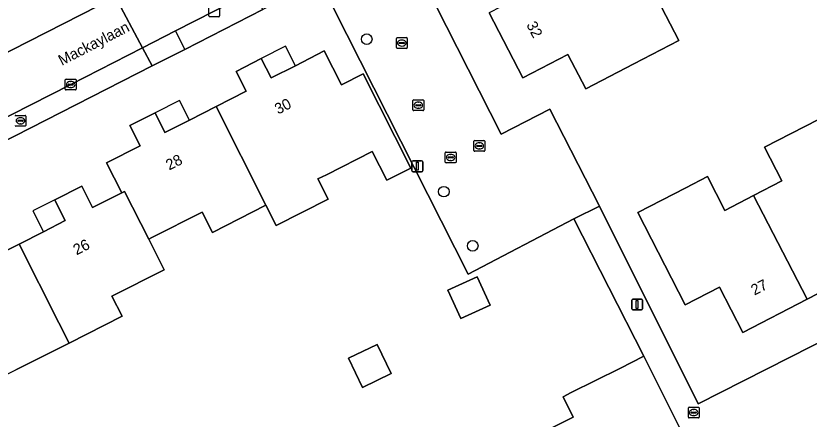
# Model space of a CAD drawing. Extents: x 162722 to 165104, y 384719 to 386284.
# Drawn here: x 163852.8 to 163926.1, y 385053.7 to 385090.9 of the extents above; entities that cross this region are included whole.
import ezdxf

# ---------------------------------------------------------------- set-up
doc = ezdxf.new("R2010")
doc.units = 0
for name, color, linetype in [('IMGEO_Boom', 7, 'Continuous'), ('IMGEO_Brandkraan', 7, 'Continuous'), ('IMGEO_Erf', 7, 'Continuous'), ('IMGEO_Kolk', 7, 'Continuous'), ('IMGEO_Lichtmast', 7, 'Continuous'), ('IMGEO_Openbare_ruimte_label', 7, 'Continuous'), ('IMGEO_Pand', 7, 'Continuous'), ('IMGEO_Pand_nummerreeks', 7, 'Continuous'), ('IMGEO_Pand_overbouw', 7, 'Continuous'), ('IMGEO_Parkeervlak_open', 7, 'Continuous'), ('IMGEO_Rijbaan_lokaal_open', 7, 'Continuous'), ('IMGEO_Rioolput', 7, 'Continuous'), ('IMGEO_Voetpad_open', 7, 'Continuous')]:
    doc.layers.add(name, color=color, linetype=linetype)

msp = doc.modelspace()

# ---------------------------------------------------------------- linework, layer by layer
at = {"layer": 'IMGEO_Boom'}
for centre in [(163885.184, 385088.775), (163892.305, 385074.695), (163894.978, 385069.688)]:
    msp.add_circle(centre, 0.489, dxfattribs=at)
at = {"layer": 'IMGEO_Brandkraan'}
for p, q in [((163852.761, 385081.738), (163853.613, 385081.738)), ((163852.945, 385081.232), (163852.945, 385081.244)), ((163853.383, 385081.195), (163852.985, 385081.195)), ((163852.988, 385081.281), (163853.386, 385081.281)), ((163853.174, 385081.518), (163853.199, 385081.518)), ((163853.429, 385081.244), (163853.429, 385081.232)), ((163853.687, 385081.664), (163853.687, 385080.812)), ((163853.613, 385080.738), (163852.761, 385080.738)), ((163853.197, 385080.958), (163853.172, 385080.958)), ((163914.978, 385054.796), (163915.83, 385054.796)), ((163914.903, 385053.87), (163914.903, 385054.722)), ((163915.162, 385054.29), (163915.162, 385054.302)), ((163915.6, 385054.253), (163915.202, 385054.253)), ((163915.205, 385054.339), (163915.603, 385054.339)), ((163915.391, 385054.576), (163915.416, 385054.576)), ((163915.646, 385054.302), (163915.646, 385054.29)), ((163915.904, 385054.722), (163915.904, 385053.87)), ((163915.83, 385053.796), (163914.978, 385053.796)), ((163915.414, 385054.016), (163915.389, 385054.016))]:
    msp.add_line(p, q, dxfattribs=at)
for points in [[(163852.761, 385081.738), (163853.613, 385081.738)], [(163853.687, 385081.664), (163853.687, 385080.812)], [(163853.613, 385080.738), (163852.761, 385080.738)], [(163914.978, 385054.796), (163915.83, 385054.796)], [(163914.903, 385053.87), (163914.903, 385054.722)], [(163915.904, 385054.722), (163915.904, 385053.87)], [(163915.83, 385053.796), (163914.978, 385053.796)]]:
    msp.add_lwpolyline(points, dxfattribs=at)
for centre, radius, start, end in [((163852.763, 385081.662), 0.0765, 91.55205, 178.44795), ((163852.763, 385081.662), 0.0765, 91.55205, 178.44795), ((163852.985, 385081.241), 0.0403, 85.87752, 175.75265), ((163852.982, 385081.231), 0.0366, 178.93798, 274.71019), ((163853.386, 385081.238), 0.043, 264.86636, 352.45326), ((163853.39, 385081.243), 0.0386, 1.73085, 96.63898), ((163853.611, 385081.662), 0.0765, 1.55205, 88.44795), ((163853.611, 385081.662), 0.0765, 1.55205, 88.44795), ((163852.763, 385080.814), 0.0765, 181.55205, 268.44795), ((163852.763, 385080.814), 0.0765, 181.55205, 268.44795), ((163853.611, 385080.814), 0.0765, 271.55205, 358.44795), ((163853.611, 385080.814), 0.0765, 271.55205, 358.44795), ((163914.98, 385054.72), 0.0765, 91.55205, 178.44795), ((163914.98, 385054.72), 0.0765, 91.55205, 178.44795), ((163915.828, 385054.72), 0.0765, 1.55205, 88.44795), ((163915.828, 385054.72), 0.0765, 1.55205, 88.44795), ((163915.202, 385054.299), 0.0403, 85.87752, 175.75265), ((163915.199, 385054.289), 0.0366, 178.93798, 274.71019), ((163915.603, 385054.296), 0.043, 264.86636, 352.45326), ((163915.607, 385054.301), 0.0386, 1.73085, 96.63898), ((163914.98, 385053.872), 0.0765, 181.55205, 268.44795), ((163914.98, 385053.872), 0.0765, 181.55205, 268.44795), ((163915.828, 385053.872), 0.0765, 271.55205, 358.44795), ((163915.828, 385053.872), 0.0765, 271.55205, 358.44795)]:
    msp.add_arc(centre, radius, start, end, dxfattribs=at)
for centre, major_axis, ratio, start_param, end_param in [((163853.173, 385081.238), (-0.387, 0.002), 0.722429, 4.712389, 7.853982), ((163853.198, 385081.238), (-0.39, 0.002), 0.717154, 1.570796, 4.712389), ((163915.39, 385054.296), (-0.387, 0.002), 0.722429, 4.712389, 7.853982), ((163915.415, 385054.296), (-0.39, 0.002), 0.717154, 1.570796, 4.712389)]:
    msp.add_ellipse(centre, major_axis=major_axis, ratio=ratio, start_param=start_param, end_param=end_param, dxfattribs=at)
at = {"layer": 'IMGEO_Erf'}
for points in [[(163882.314, 385121.11), (163885.455, 385114.979), (163893.028, 385100.308), (163888.495, 385097.974), (163897.601, 385079.99), (163902.096, 385082.296), (163906.672, 385073.409), (163906.693, 385073.366), (163915.816, 385055.107), (163938.946, 385066.833)], [(163844.323, 385083.699), (163845.913, 385084.495), (163861.973, 385092.689), (163879.735, 385101.752)], [(163910.786, 385094.89), (163914.022, 385088.652), (163909.858, 385086.492), (163905.419, 385084.19), (163903.77, 385087.369), (163899.61, 385085.211), (163896.499, 385091.208)], [(163899.686, 385051.591), (163904.266, 385053.887), (163903.329, 385055.755), (163904.089, 385056.136), (163908.558, 385058.376), (163910.795, 385059.494), (163904.326, 385072.183), (163894.544, 385067.072), (163880.854, 385094.169), (163878.622, 385093.046), (163875.596, 385091.501), (163868.387, 385087.828), (163865.359, 385086.309), (163851.324, 385079.151)], [(163850.057, 385068.328), (163853.059, 385069.852), (163855.314, 385070.997), (163857.331, 385072.021), (163856.376, 385073.904), (163856.356, 385073.944), (163858.844, 385075.207), (163859.85, 385073.227), (163862.538, 385074.592), (163861.139, 385077.348), (163864.257, 385078.931), (163863.307, 385080.802), (163865.619, 385081.976), (163866.538, 385080.166), (163868.8, 385081.297), (163871.258, 385082.545), (163874.042, 385083.959), (163873.106, 385085.803), (163875.44, 385086.989), (163876.354, 385085.191), (163878.589, 385086.326), (163881.259, 385087.682), (163882.849, 385084.552), (163884.865, 385085.567), (163889.273, 385076.87), (163887.04, 385075.746), (163885.687, 385078.414), (163881.451, 385076.263), (163880.671, 385075.867), (163881.617, 385074.004), (163876.82, 385071.568), (163875.874, 385073.435), (163870.931, 385070.924), (163869.976, 385072.803), (163865.335, 385070.447), (163865.034, 385070.295), (163866.457, 385067.487), (163861.641, 385065.042), (163862.579, 385063.193), (163857.691, 385060.711), (163852.747, 385058.247)]]:
    msp.add_lwpolyline(points, dxfattribs=at)
for points in [[(163932.499, 385073.497), (163929.642, 385072.024), (163931.809, 385067.822), (163925.868, 385064.758), (163919.927, 385061.695), (163917.775, 385065.867), (163914.617, 385064.238), (163910.224, 385072.757), (163914.668, 385075.049), (163916.677, 385076.085), (163918.286, 385072.966), (163920.934, 385074.332), (163923.551, 385075.682), (163921.948, 385078.788), (163928.127, 385081.975), (163930.207, 385077.941)], [(163892.693, 385065.585), (163895.401, 385066.822), (163896.589, 385064.222), (163893.881, 385062.985)], [(163883.496, 385059.309), (163886.14, 385060.596), (163887.449, 385057.906), (163884.805, 385056.62)]]:
    msp.add_lwpolyline(points, close=True, dxfattribs=at)
at = {"layer": 'IMGEO_Kolk'}
for p, q in [((163870.591, 385090.925), (163870.591, 385091.777)), ((163871.592, 385091.777), (163871.592, 385090.925)), ((163871.518, 385090.851), (163870.666, 385090.851)), ((163887.927, 385087.99), (163887.927, 385088.842)), ((163888.002, 385088.916), (163888.854, 385088.916)), ((163888.415, 385088.696), (163888.44, 385088.696)), ((163888.928, 385088.842), (163888.928, 385087.99)), ((163888.854, 385087.916), (163888.002, 385087.916)), ((163888.186, 385088.41), (163888.186, 385088.422)), ((163888.624, 385088.373), (163888.226, 385088.373)), ((163888.229, 385088.459), (163888.627, 385088.459)), ((163888.438, 385088.136), (163888.413, 385088.136)), ((163888.67, 385088.422), (163888.67, 385088.41)), ((163857.33, 385084.156), (163857.33, 385085.008)), ((163857.405, 385085.082), (163858.257, 385085.082)), ((163857.818, 385084.862), (163857.843, 385084.862)), ((163858.331, 385085.008), (163858.331, 385084.156)), ((163857.589, 385084.576), (163857.589, 385084.588)), ((163858.027, 385084.539), (163857.629, 385084.539)), ((163857.632, 385084.625), (163858.03, 385084.625)), ((163857.841, 385084.302), (163857.816, 385084.302)), ((163858.073, 385084.588), (163858.073, 385084.576)), ((163858.257, 385084.082), (163857.405, 385084.082)), ((163895.083, 385078.494), (163895.083, 385079.346)), ((163895.158, 385079.42), (163896.01, 385079.42)), ((163895.385, 385078.963), (163895.783, 385078.963)), ((163895.571, 385079.2), (163895.596, 385079.2)), ((163896.084, 385079.346), (163896.084, 385078.494)), ((163896.01, 385078.42), (163895.158, 385078.42)), ((163895.342, 385078.914), (163895.342, 385078.926)), ((163895.78, 385078.877), (163895.382, 385078.877)), ((163895.594, 385078.64), (163895.569, 385078.64)), ((163895.826, 385078.926), (163895.826, 385078.914))]:
    msp.add_line(p, q, dxfattribs=at)
for points in [[(163870.591, 385090.925), (163870.591, 385091.777)], [(163871.592, 385091.777), (163871.592, 385090.925)], [(163871.518, 385090.851), (163870.666, 385090.851)], [(163887.927, 385087.99), (163887.927, 385088.842)], [(163888.002, 385088.916), (163888.854, 385088.916)], [(163888.928, 385088.842), (163888.928, 385087.99)], [(163888.854, 385087.916), (163888.002, 385087.916)], [(163857.33, 385084.156), (163857.33, 385085.008)], [(163857.405, 385085.082), (163858.257, 385085.082)], [(163858.331, 385085.008), (163858.331, 385084.156)], [(163858.257, 385084.082), (163857.405, 385084.082)], [(163895.083, 385078.494), (163895.083, 385079.346)], [(163895.158, 385079.42), (163896.01, 385079.42)], [(163896.084, 385079.346), (163896.084, 385078.494)], [(163896.01, 385078.42), (163895.158, 385078.42)]]:
    msp.add_lwpolyline(points, dxfattribs=at)
for centre, radius, start, end in [((163870.668, 385090.927), 0.0765, 181.55205, 268.44795), ((163870.668, 385090.927), 0.0765, 181.55205, 268.44795), ((163871.516, 385090.927), 0.0765, 271.55205, 358.44795), ((163871.516, 385090.927), 0.0765, 271.55205, 358.44795), ((163888.004, 385088.84), 0.0765, 91.55205, 178.44795), ((163888.004, 385088.84), 0.0765, 91.55205, 178.44795), ((163888.852, 385088.84), 0.0765, 1.55205, 88.44795), ((163888.852, 385088.84), 0.0765, 1.55205, 88.44795), ((163888.004, 385087.992), 0.0765, 181.55205, 268.44795), ((163888.004, 385087.992), 0.0765, 181.55205, 268.44795), ((163888.226, 385088.419), 0.0403, 85.87752, 175.75265), ((163888.223, 385088.409), 0.0366, 178.93798, 274.71019), ((163888.627, 385088.416), 0.043, 264.86636, 352.45326), ((163888.631, 385088.421), 0.0386, 1.73085, 96.63898), ((163888.852, 385087.992), 0.0765, 271.55205, 358.44795), ((163888.852, 385087.992), 0.0765, 271.55205, 358.44795), ((163857.407, 385085.006), 0.0765, 91.55205, 178.44795), ((163857.407, 385085.006), 0.0765, 91.55205, 178.44795), ((163858.255, 385085.006), 0.0765, 1.55205, 88.44795), ((163858.255, 385085.006), 0.0765, 1.55205, 88.44795), ((163857.407, 385084.158), 0.0765, 181.55205, 268.44795), ((163857.407, 385084.158), 0.0765, 181.55205, 268.44795), ((163857.629, 385084.585), 0.0403, 85.87752, 175.75265), ((163857.626, 385084.575), 0.0366, 178.93798, 274.71019), ((163858.03, 385084.582), 0.043, 264.86636, 352.45326), ((163858.034, 385084.587), 0.0386, 1.73085, 96.63898), ((163858.255, 385084.158), 0.0765, 271.55205, 358.44795), ((163858.255, 385084.158), 0.0765, 271.55205, 358.44795), ((163895.16, 385079.344), 0.0765, 91.55205, 178.44795), ((163895.16, 385079.344), 0.0765, 91.55205, 178.44795), ((163895.382, 385078.923), 0.0403, 85.87752, 175.75265), ((163895.787, 385078.925), 0.0386, 1.73085, 96.63898), ((163896.008, 385079.344), 0.0765, 1.55205, 88.44795), ((163896.008, 385079.344), 0.0765, 1.55205, 88.44795), ((163895.16, 385078.496), 0.0765, 181.55205, 268.44795), ((163895.16, 385078.496), 0.0765, 181.55205, 268.44795), ((163895.379, 385078.913), 0.0366, 178.93798, 274.71019), ((163895.783, 385078.92), 0.043, 264.86636, 352.45326), ((163896.008, 385078.496), 0.0765, 271.55205, 358.44795), ((163896.008, 385078.496), 0.0765, 271.55205, 358.44795)]:
    msp.add_arc(centre, radius, start, end, dxfattribs=at)
for centre, major_axis, ratio, start_param, end_param in [((163888.414, 385088.416), (-0.387, 0.002), 0.722429, 4.712389, 7.853982), ((163888.439, 385088.416), (-0.39, 0.002), 0.717154, 1.570796, 4.712389), ((163857.817, 385084.582), (-0.387, 0.002), 0.722429, 4.712389, 7.853982), ((163857.842, 385084.582), (-0.39, 0.002), 0.717154, 1.570796, 4.712389), ((163895.57, 385078.92), (-0.387, 0.002), 0.722429, 4.712389, 7.853982), ((163895.595, 385078.92), (-0.39, 0.002), 0.717154, 1.570796, 4.712389)]:
    msp.add_ellipse(centre, major_axis=major_axis, ratio=ratio, start_param=start_param, end_param=end_param, dxfattribs=at)
at = {"layer": 'IMGEO_Lichtmast'}
for p, q in [((163889.464, 385077.54), (163890.254, 385077.54)), ((163890.254, 385077.54), (163889.464, 385077.54)), ((163889.364, 385076.64), (163889.364, 385077.44)), ((163889.364, 385077.44), (163889.364, 385076.64)), ((163890.354, 385077.44), (163890.354, 385076.64)), ((163890.354, 385076.64), (163890.354, 385077.44)), ((163890.254, 385076.54), (163889.464, 385076.54)), ((163889.464, 385076.54), (163890.254, 385076.54)), ((163909.671, 385063.876), (163909.671, 385064.676)), ((163909.671, 385064.676), (163909.671, 385063.876)), ((163909.771, 385064.776), (163910.561, 385064.776)), ((163910.561, 385064.776), (163909.771, 385064.776)), ((163910.661, 385064.676), (163910.661, 385063.876)), ((163910.661, 385063.876), (163910.661, 385064.676)), ((163910.561, 385063.776), (163909.771, 385063.776)), ((163909.771, 385063.776), (163910.561, 385063.776))]:
    msp.add_line(p, q, dxfattribs=at)
for points in [[(163889.784, 385077.415), (163889.934, 385077.415), (163889.934, 385076.665), (163889.784, 385076.665), (163889.784, 385077.415)], [(163910.091, 385064.651), (163910.241, 385064.651), (163910.241, 385063.901), (163910.091, 385063.901), (163910.091, 385064.651)]]:
    msp.add_lwpolyline(points, dxfattribs=at)
for centre, start, end in [((163889.464, 385077.44), 90, 180), ((163889.464, 385077.44), 90, 180), ((163890.254, 385077.44), 0, 90), ((163890.254, 385077.44), 360, 90), ((163889.464, 385076.64), 180, 270), ((163889.464, 385076.64), 180, 270), ((163890.254, 385076.64), 270, 0), ((163890.254, 385076.64), 270, 0), ((163909.771, 385064.676), 90, 180), ((163909.771, 385064.676), 90, 180), ((163910.561, 385064.676), 0, 90), ((163910.561, 385064.676), 360, 90), ((163909.771, 385063.876), 180, 270), ((163909.771, 385063.876), 180, 270), ((163910.561, 385063.876), 270, 0), ((163910.561, 385063.876), 270, 0)]:
    msp.add_arc(centre, 0.1, start, end, dxfattribs=at)
at = {"layer": 'IMGEO_Pand'}
for points in [[(163896.499, 385091.208), (163899.61, 385085.211), (163903.77, 385087.369), (163905.419, 385084.19), (163909.858, 385086.492), (163914.022, 385088.652), (163910.786, 385094.89), (163907.719, 385093.299), (163906.196, 385096.235)], [(163884.865, 385085.567), (163882.849, 385084.552), (163881.259, 385087.682), (163878.589, 385086.326), (163876.354, 385085.191), (163875.44, 385086.989), (163873.106, 385085.803), (163874.042, 385083.959), (163871.258, 385082.545), (163875.874, 385073.435), (163876.82, 385071.568), (163881.617, 385074.004), (163880.671, 385075.867), (163881.451, 385076.263), (163885.687, 385078.414), (163887.04, 385075.746), (163889.273, 385076.87)], [(163871.258, 385082.545), (163868.8, 385081.297), (163866.538, 385080.166), (163865.619, 385081.976), (163863.307, 385080.802), (163864.257, 385078.931), (163861.139, 385077.348), (163862.538, 385074.592), (163862.792, 385074.721), (163865.034, 385070.295), (163865.335, 385070.447), (163869.976, 385072.803), (163870.931, 385070.924), (163875.874, 385073.435)], [(163931.809, 385067.822), (163929.642, 385072.024), (163932.499, 385073.497), (163930.207, 385077.941), (163928.127, 385081.975), (163921.948, 385078.788), (163923.551, 385075.682), (163920.934, 385074.332), (163925.868, 385064.758)], [(163920.934, 385074.332), (163918.286, 385072.966), (163916.677, 385076.085), (163914.668, 385075.049), (163910.224, 385072.757), (163914.617, 385064.238), (163917.775, 385065.867), (163919.927, 385061.695), (163925.868, 385064.758)], [(163865.034, 385070.295), (163862.792, 385074.721), (163862.538, 385074.592), (163859.85, 385073.227), (163858.844, 385075.207), (163856.356, 385073.944), (163856.376, 385073.904), (163857.331, 385072.021), (163855.314, 385070.997), (163853.059, 385069.852), (163856.741, 385062.586), (163857.691, 385060.711), (163862.579, 385063.193), (163861.641, 385065.042), (163866.457, 385067.487)], [(163857.691, 385060.711), (163856.741, 385062.586), (163853.059, 385069.852), (163850.057, 385068.328), (163849.067, 385070.277), (163846.484, 385068.966), (163847.437, 385067.09), (163845.555, 385066.134), (163843.179, 385064.927), (163847.83, 385055.75), (163852.747, 385058.247)], [(163892.693, 385065.585), (163893.881, 385062.985), (163896.589, 385064.222), (163895.401, 385066.822)], [(163883.496, 385059.309), (163884.805, 385056.62), (163887.449, 385057.906), (163886.14, 385060.596)], [(163914.793, 385051.52), (163914.717, 385051.672), (163910.795, 385059.494), (163908.558, 385058.376), (163904.089, 385056.136), (163903.329, 385055.755), (163904.266, 385053.887), (163899.686, 385051.591), (163899.337, 385051.416), (163903.035, 385044.103), (163906.066, 385045.623), (163906.98, 385043.8), (163911.431, 385046.031), (163910.484, 385047.92), (163913.134, 385049.248), (163912.557, 385050.399)]]:
    msp.add_lwpolyline(points, close=True, dxfattribs=at)
at = {"layer": 'IMGEO_Pand_overbouw'}
for points in [[(163877.676, 385088.124), (163875.44, 385086.989), (163876.354, 385085.191), (163878.589, 385086.326)], [(163867.874, 385083.121), (163865.619, 385081.976), (163866.538, 385080.166), (163868.8, 385081.297)], [(163856.356, 385073.944), (163854.339, 385072.919), (163855.314, 385070.997), (163857.331, 385072.021)]]:
    msp.add_lwpolyline(points, close=True, dxfattribs=at)
at = {"layer": 'IMGEO_Parkeervlak_open'}
for points in [[(163888.495, 385097.974), (163880.854, 385094.169), (163894.544, 385067.072), (163904.326, 385072.183), (163906.693, 385073.366), (163906.672, 385073.409), (163902.096, 385082.296), (163897.601, 385079.99)], [(163940.84, 385056.735), (163939.815, 385059.02), (163942.387, 385060.349), (163941.615, 385061.804), (163938.946, 385066.833), (163915.816, 385055.107), (163906.693, 385073.366), (163904.326, 385072.183), (163910.795, 385059.494), (163914.717, 385051.672), (163914.888, 385051.766), (163918.27, 385045.174)]]:
    msp.add_lwpolyline(points, close=True, dxfattribs=at)
at = {"layer": 'IMGEO_Rijbaan_lokaal_open'}
for points in [[(163879.735, 385101.752), (163861.973, 385092.689), (163864.465, 385087.985), (163867.517, 385089.529), (163871.092, 385091.351), (163874.733, 385093.213), (163877.744, 385094.776), (163881.918, 385096.889)], [(163857.831, 385084.582), (163864.465, 385087.985), (163861.973, 385092.689), (163845.913, 385084.495), (163844.323, 385083.699)], [(163843.22, 385077.171), (163844.941, 385078.045), (163847.873, 385079.556), (163850.467, 385080.873), (163857.831, 385084.582)]]:
    msp.add_lwpolyline(points, dxfattribs=at)
at = {"layer": 'IMGEO_Rioolput'}
for p, q in [((163889.45, 385082.251), (163889.45, 385083.103)), ((163889.525, 385083.177), (163890.377, 385083.177)), ((163889.709, 385082.671), (163889.709, 385082.683)), ((163890.147, 385082.634), (163889.749, 385082.634)), ((163889.752, 385082.72), (163890.15, 385082.72)), ((163889.938, 385082.957), (163889.963, 385082.957)), ((163890.193, 385082.683), (163890.193, 385082.671)), ((163890.451, 385083.103), (163890.451, 385082.251)), ((163890.377, 385082.177), (163889.525, 385082.177)), ((163889.961, 385082.397), (163889.936, 385082.397)), ((163892.444, 385077.427), (163892.444, 385078.279)), ((163892.519, 385078.353), (163893.371, 385078.353)), ((163893.445, 385078.279), (163893.445, 385077.427)), ((163892.703, 385077.847), (163892.703, 385077.859)), ((163893.141, 385077.81), (163892.743, 385077.81)), ((163892.746, 385077.896), (163893.144, 385077.896)), ((163892.955, 385077.573), (163892.93, 385077.573)), ((163892.932, 385078.133), (163892.957, 385078.133)), ((163893.187, 385077.859), (163893.187, 385077.847)), ((163893.371, 385077.353), (163892.519, 385077.353))]:
    msp.add_line(p, q, dxfattribs=at)
for points in [[(163889.45, 385082.251), (163889.45, 385083.103)], [(163889.525, 385083.177), (163890.377, 385083.177)], [(163890.451, 385083.103), (163890.451, 385082.251)], [(163890.377, 385082.177), (163889.525, 385082.177)], [(163892.444, 385077.427), (163892.444, 385078.279)], [(163892.519, 385078.353), (163893.371, 385078.353)], [(163893.445, 385078.279), (163893.445, 385077.427)], [(163893.371, 385077.353), (163892.519, 385077.353)]]:
    msp.add_lwpolyline(points, dxfattribs=at)
for centre, radius, start, end in [((163889.527, 385083.101), 0.0765, 91.55205, 178.44795), ((163889.527, 385083.101), 0.0765, 91.55205, 178.44795), ((163889.749, 385082.68), 0.0403, 85.87752, 175.75265), ((163889.746, 385082.67), 0.0366, 178.93798, 274.71019), ((163890.15, 385082.677), 0.043, 264.86636, 352.45326), ((163890.154, 385082.682), 0.0386, 1.73085, 96.63898), ((163890.375, 385083.101), 0.0765, 1.55205, 88.44795), ((163890.375, 385083.101), 0.0765, 1.55205, 88.44795), ((163889.527, 385082.253), 0.0765, 181.55205, 268.44795), ((163889.527, 385082.253), 0.0765, 181.55205, 268.44795), ((163890.375, 385082.253), 0.0765, 271.55205, 358.44795), ((163890.375, 385082.253), 0.0765, 271.55205, 358.44795), ((163892.521, 385078.277), 0.0765, 91.55205, 178.44795), ((163892.521, 385078.277), 0.0765, 91.55205, 178.44795), ((163893.369, 385078.277), 0.0765, 1.55205, 88.44795), ((163893.369, 385078.277), 0.0765, 1.55205, 88.44795), ((163892.743, 385077.856), 0.0403, 85.87752, 175.75265), ((163892.74, 385077.846), 0.0366, 178.93798, 274.71019), ((163893.144, 385077.853), 0.043, 264.86636, 352.45326), ((163893.148, 385077.858), 0.0386, 1.73085, 96.63898), ((163892.521, 385077.429), 0.0765, 181.55205, 268.44795), ((163892.521, 385077.429), 0.0765, 181.55205, 268.44795), ((163893.369, 385077.429), 0.0765, 271.55205, 358.44795), ((163893.369, 385077.429), 0.0765, 271.55205, 358.44795)]:
    msp.add_arc(centre, radius, start, end, dxfattribs=at)
for centre, major_axis, ratio, start_param, end_param in [((163889.937, 385082.677), (-0.387, 0.002), 0.722429, 4.712389, 7.853982), ((163889.962, 385082.677), (-0.39, 0.002), 0.717154, 1.570796, 4.712389), ((163892.931, 385077.853), (-0.387, 0.002), 0.722429, 4.712389, 7.853982), ((163892.956, 385077.853), (-0.39, 0.002), 0.717154, 1.570796, 4.712389)]:
    msp.add_ellipse(centre, major_axis=major_axis, ratio=ratio, start_param=start_param, end_param=end_param, dxfattribs=at)
at = {"layer": 'IMGEO_Voetpad_open'}
for points in [[(163874.733, 385093.213), (163871.092, 385091.351), (163867.517, 385089.529), (163868.387, 385087.828), (163875.596, 385091.501)], [(163865.359, 385086.309), (163868.387, 385087.828), (163867.517, 385089.529), (163864.465, 385087.985)], [(163851.324, 385079.151), (163865.359, 385086.309), (163864.465, 385087.985), (163857.831, 385084.582), (163850.467, 385080.873)]]:
    msp.add_lwpolyline(points, close=True, dxfattribs=at)

# ---------------------------------------------------------------- texts
at = {"layer": 'IMGEO_Openbare_ruimte_label'}
msp.add_text('Mackaylaan', height=1, rotation=27.20592, dxfattribs=at).set_placement((163857.006, 385086.303))
at = {"layer": 'IMGEO_Pand_nummerreeks'}
for s, rotation, p in [('32', 297.41845, (163899.909, 385090.106)), ('30', 27.18685, (163876.995, 385081.804)), ('28', 27.18685, (163866.935, 385076.637)), ('26', 26.82015, (163858.369, 385068.81)), ('27', 27.27807, (163921.007, 385065.087))]:
    msp.add_text(s, height=1, rotation=rotation, dxfattribs=at).set_placement(p)

doc.saveas('drawing.dxf')
